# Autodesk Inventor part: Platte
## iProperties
Shininess: 64.0
Length Units: 11269
Angle Units: 11279
Time Units: 11290
Mass Units: 11283
Length Display Precision: 3
Angle Display Precision: 2
Compacted: True
Part Number: Platte
Document SubType Name: Modeling
Created: 2004-05
Material: Standard
Designer: mp
Density: 0.0
Volumn: 0.0
Area: 0.0
PropertySet Name: Model Information
Control State: 0
Master: False
Checked Out: False
Author: mp
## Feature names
1. Extrusion1
2. Fase1 [Chamfer]
